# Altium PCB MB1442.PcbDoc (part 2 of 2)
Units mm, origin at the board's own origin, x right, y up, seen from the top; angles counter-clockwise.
Board outline 18.54 x 50.29 mm, 4 copper layers (Top Layer, Signal Layer 1, Signal Layer 2, Bottom Layer); 93 components, 78 nets, 322 pads, 169 vias.
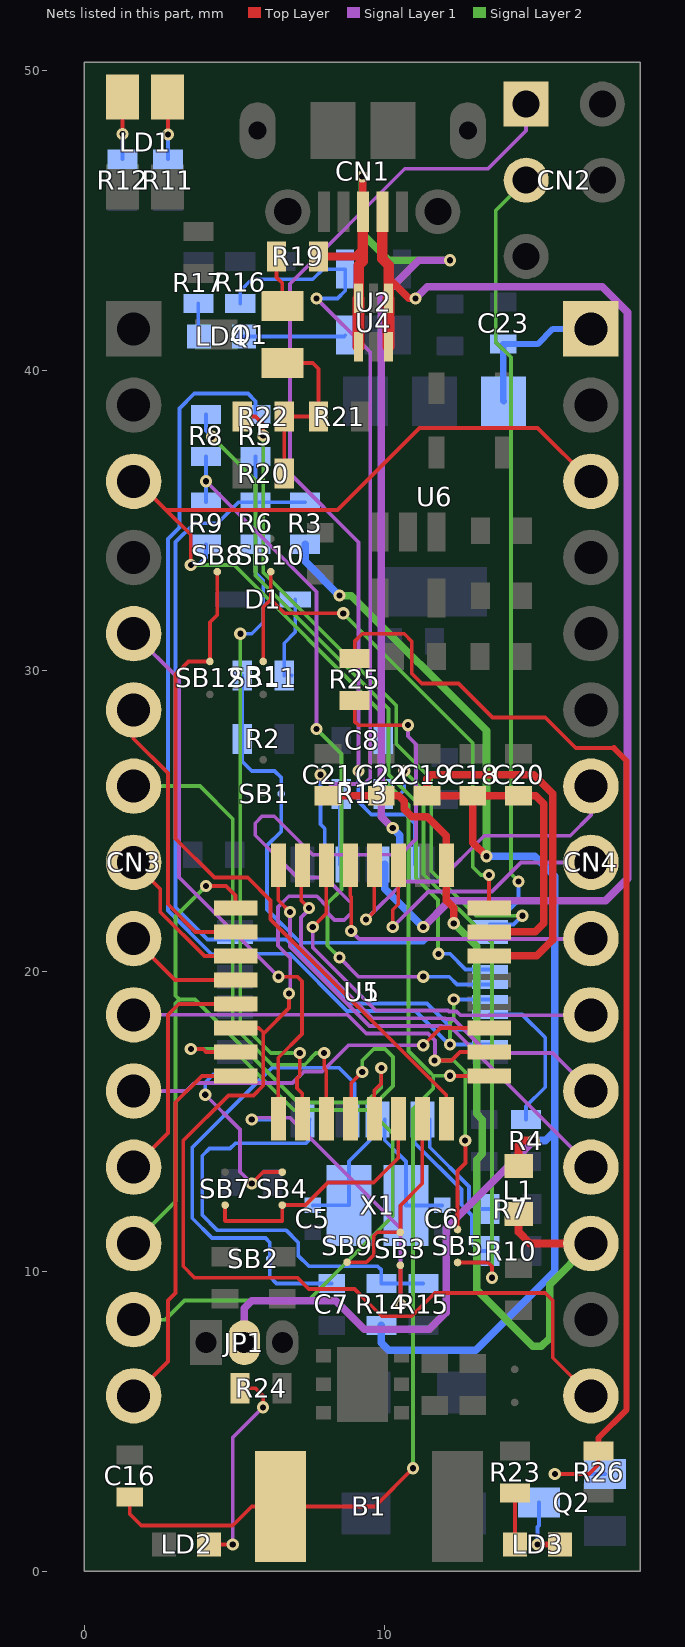
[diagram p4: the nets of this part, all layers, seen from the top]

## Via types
v1: diameter 0.406, hole 0.203, Top Layer to Bottom Layer, tented both sides, 169 vias

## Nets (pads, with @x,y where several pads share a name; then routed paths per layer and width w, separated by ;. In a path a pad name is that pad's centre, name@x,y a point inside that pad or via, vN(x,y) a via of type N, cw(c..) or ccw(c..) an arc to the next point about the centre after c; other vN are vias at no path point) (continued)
NetD1_2: D1.2 R1.1 | length 2.7
  Bottom Layer w0.127: R1.1@6.669,29.845 6.669,30.926 7.039,31.296 D1.2@7.039,32.385 ; R1.1@6.912,29.856 R1.1@6.923,29.845
NetLD1_2: LD1.2 R12.2 | length 2.1
  Top Layer w0.127: v1(1.282,47.891) LD1.2@1.282,49.125
  Bottom Layer w0.127: R12.2@1.282,47.055 v1(1.282,47.891)
NetLD1_3: LD1.3 R11.2 | length 2.1
  Top Layer w0.127: v1(2.794,47.879) LD1.3@2.794,49.113
  Bottom Layer w0.127: R11.2@2.794,47.055 v1(2.794,47.879)
NetLD2_1: LD2.1 R24.1 | length 7
  Top Layer w0.127: LD2.1@4.167,0.889 v1(4.953,0.889) ; R24.1@5.2,6.096 5.715,6.096 5.969,5.842 5.969,5.468 v1(5.962,5.461)
  Signal Layer 1 w0.127: v1(4.953,0.889) 4.953,4.452 v1(5.962,5.461)
NetLD3_1: LD3.1 R23.1 | length 1.7
  Top Layer w0.127: LD3.1@14.363,0.889 R23.1@14.363,2.602
NetLD3_2: LD3.2 Q2.3 | length 2.2
  Top Layer w0.203: v1(15.113,0.889) LD3.2@15.863,0.889
  Bottom Layer w0.127: v1(15.113,0.889) 15.113,1.481 15.156,1.524 Q2.3@15.156,2.286
NetLD4_1: LD4.1 R17.1 | length 1.1
  Bottom Layer w0.127: R17.1@3.807,42.245 3.807,41.163 LD4.1@3.822,41.148
NetLD4_2: LD4.2 U2.3 | length 3.4
  Bottom Layer w0.127: LD4.2@5.322,41.148 8.659,41.148 U2.3@8.702,41.191
NetQ1_1: Q1.1 R20.1 R21.2 R22.1 | length 6
  Top Layer w0.127: Q1.1@6.604,40.259 7.62,40.259 7.809,40.07 R21.2@7.809,38.481 R22.1@6.669,38.481 R20.1@6.669,36.576 ; Q1.1@6.604,40.518 Q1.1@6.669,40.453
NetQ1_2: Q1.2 R19.2 | length 1.7
  Top Layer w0.127: R19.2@6.412,43.815 6.412,43.118 6.604,42.926 Q1.2@6.604,42.159
NetQ2_1: Q2.1 R25.2 R26.1 | length 39.2
  Top Layer w0.127: R25.2@9.017,30.418 9.017,30.988 9.271,31.242 10.668,31.242 10.922,30.988 10.922,29.913 11.252,29.583 12.476,29.583 13.611,28.448 15.367,28.448 16.383,27.432 17.653,27.432 ; v1(15.687,3.236) 16.825,3.236 17.145,3.556 R26.1@17.145,4.002
  Top Layer w0.2: R26.1@17.145,4.002 17.145,4.445 18.083,5.383 18.083,27.002 17.653,27.432
  Bottom Layer w0.127: v1(15.687,3.236) Q2.1@17.356,3.236
NetR1_2: R1.2 R2.1 SB1.2 U1.39 | length 16.9
  Bottom Layer w0.127: R1.2@5.269,29.845 R2.1@5.269,27.734 5.269,26.989 5.588,26.67 6.35,26.67 6.569,26.451 SB1.2@6.569,25.908 6.569,24.652 6.096,24.179 6.096,22.054 7.208,20.942 11.318,20.942 11.455,21.079 13.496,21.079 U1.39@13.521,21.054
NetR4_2: R4.2 U1.44 | length 5.2
  Bottom Layer w0.127: U1.44@13.521,18.554 14.593,18.554 15.367,17.78 15.367,16.129 14.732,15.494 R4.2@14.732,15.051
NetR7_2: R7.2 U1.2 | length 4.1
  Bottom Layer w0.127: U1.2@11.521,15.054 11.521,14.129 12.827,12.823 12.827,12.319 13.081,12.065 R7.2@13.524,12.065
NetR10_2: R10.2 U1.3 | length 5.6
  Bottom Layer w0.127: U1.3@11.021,15.054 11.021,14.269 12.573,12.717 12.573,12.214 12.929,11.857 12.929,10.922 13.183,10.668 R10.2@13.524,10.668
NetR13_1: R13.1 U1.29 | length 2.4
  Bottom Layer w0.127: U1.29@8.521,23.554 8.521,25.858 R13.1@8.571,25.908
NetR14_2: R14.2 R15.2 U1.10 | length 15.3
  Bottom Layer w0.127: U1.10@7.521,15.054 7.493,15.026 7.493,14.364 7.393,14.263 5.041,14.263 4.862,14.084 4.178,14.084 3.937,13.843 3.937,11.866 4.445,11.358 6.74,11.358 7.134,10.964 7.134,10.519 7.493,10.16 9.779,10.16 9.906,10.033 R14.2@9.906,9.59 R15.2@11.303,9.59
NetSB3_2: SB3.2 U1.12 | length 11.3
  Top Layer w0.127: v1(10.541,8.89) SB3.2@10.541,10.195
  Signal Layer 1 w0.127: v1@5.588,15.113 6.858,15.113 10.541,11.43 v1(10.541,8.89)
  Bottom Layer w0.127: v1(5.588,15.054) U1.12@6.521,15.054
NetSB4_2: SB4.2 U1.13 | length 6.4
  Top Layer w0.127: v1(5.588,12.919) 5.969,13.3 SB4.2@6.604,13.3
  Signal Layer 1 w0.127: v1(4.038,15.877) 5.194,14.721 5.194,13.313 v1(5.588,12.919)
  Bottom Layer w0.127: v1@4.063,15.852 4.085,15.875 4.084,15.877 v1(4.038,15.877) 4.038,16.29 4.302,16.554 U1.13@5.021,16.554
PA1: CN3.10 SB5.2 U5.2 | length 20.5
  Top Layer w0.127: v1(11.684,17.018) 12.241,17.018 12.527,17.304 U5.2@13.496,17.304 ; SB5.2@12.446,11.387 12.446,13.335 12.713,13.602 12.713,14.465 12.7,14.453 v1(12.7,14.351)
  Signal Layer 1 w0.127: CN3.10@2.159,18.034 CN3.10@1.651,18.542 8.78,18.542 9.402,17.92 11.466,17.92 11.697,17.689 11.697,17.031 v1(11.684,17.018)
  Signal Layer 2 w0.127: v1(11.684,17.018) 12.319,17.018 12.7,16.637 v1(12.7,14.351)
PA2: CN3.11 U5.3 | length 12.7
  Top Layer w0.127: v1(11.303,17.526) 11.881,18.104 U5.3@13.496,18.104
  Signal Layer 1 w0.127: CN3.11@1.651,16.002 3.416,16.002 3.685,16.271 6.951,16.271 7.33,16.65 7.935,16.65 8.812,17.526 v1(11.303,17.526)
PB0: CN4.12 U5.16 | length 15.9
  Top Layer w0.127: U5.16@6.471,23.529 6.471,22.358 v1(6.858,21.971)
  Signal Layer 1 w0.127: v1(6.858,21.971) 6.858,20.823 9.507,18.174 11.92,18.174 11.946,18.148 12.205,18.148 CN4.12@16.891,13.462
PB1: CN4.11 U5.15 | length 14.6
  Top Layer w0.127: U5.15@7.271,23.529 7.239,23.497 7.239,22.352 v1(7.493,22.098)
  Signal Layer 1 w0.127: v1@7.514,22.098 v1(7.493,22.098) 7.493,22.049 7.226,21.783 7.226,20.814 9.612,18.428 12.025,18.428 12.051,18.402 12.31,18.402 13.44,17.272 15.621,17.272 CN4.11@16.891,16.002
PB2: CN4.10 U5.14 | length 13.2
  Top Layer w0.127: v1(7.62,21.463) 8.071,21.914 U5.14@8.071,23.529
  Signal Layer 1 w0.127: v1(7.62,21.463) 7.62,20.779 9.718,18.682 12.131,18.682 12.156,18.656 12.415,18.656 12.542,18.529 16.891,18.529 CN4.10@16.891,18.542
PB3: CN4.9 U5.13 | length 10.3
  Top Layer w0.127: U5.13@8.871,23.529 8.871,22.498 8.903,22.466 8.903,21.339 v1(8.9,21.336)
  Signal Layer 1 w0.127: v1@8.89,21.336 v1(8.9,21.336) 9.167,21.069 16.878,21.069 CN4.9@16.891,21.082
PB4: CN4.7 U5.12 | length 11.8
  Top Layer w0.127: v1(9.398,21.717) 9.671,21.99 U5.12@9.671,23.529
  Signal Layer 1 w0.127: v1(9.398,21.717) 10.668,22.987 11.811,22.987 13.335,24.511 16.202,24.511 16.891,25.2 CN4.7@16.891,26.162
PB5: CN4.8 U5.11 | length 9.6
  Top Layer w0.127: v1(10.287,21.463) 10.287,22.041 10.471,22.225 U5.11@10.471,23.529
  Signal Layer 1 w0.127: v1(10.287,21.463) 11.479,22.655 13.589,22.655 14.556,23.622 CN4.8@16.891,23.622
PC1: CN3.6 U5.18 | length 9.6
  Top Layer w0.127: CN3.6@1.651,28.702 1.651,27.74 2.794,26.597 2.794,22.225 3.715,21.304 U5.18@5.046,21.304
PC2: CN3.8 U5.19 | length 5.1
  Top Layer w0.127: CN3.8@1.651,23.622 2.54,22.733 2.54,21.971 4.007,20.504 U5.19@5.046,20.504
PC3: CN3.9 U5.20 | length 4
  Top Layer w0.127: CN3.9@1.651,21.082 3.029,19.704 U5.20@5.046,19.704
PC4: CN3.12 U5.21 | length 8
  Top Layer w0.127: CN3.12@1.651,13.462 2.794,14.605 2.794,18.542 3.156,18.904 U5.21@5.046,18.904
PC5: CN4.15 R25.1 U5.22 | length 52.9
  Top Layer w0.127: U5.22@5.046,18.104 5.823,18.104 5.969,17.958 5.969,17.907 ; v1(6.833,19.253) 6.833,18.771 5.969,17.907 ; R25.1@9.017,29.018 9.017,28.321 9.144,28.194 v1(10.795,28.194) ; CN4.15@16.891,5.842 15.621,7.112 15.621,9.017 15.367,9.271 11.685,9.271 10.91,8.496 9.919,8.496 9.011,9.404 7.487,9.404 7.112,9.779 3.683,9.779 3.302,10.16 3.302,14.351 4.808,15.857 5.644,15.857 5.969,16.183 5.969,17.907
  Signal Layer 1 w0.127: v1(6.833,19.253) 6.871,19.291 6.871,20.434 6.464,20.841 6.464,22.134 6.822,22.492 7.756,22.492 8.115,22.132 8.115,21.935 8.346,21.704 8.672,21.704 8.903,21.935 8.903,22.261 8.05,23.114 7.112,23.114 5.702,24.524 5.702,24.928 5.933,25.159 6.337,25.159 7.62,23.876 10.541,23.876 11.062,24.397 11.062,27.559 10.795,27.826 v1(10.795,28.194)
PC6: CN3.14 U5.23 U5.28 | length 27.7
  Top Layer w0.127: v1(3.556,17.399) 3.969,17.399 4.064,17.304 U5.23@5.046,17.304 ; U5.28@8.871,15.079 8.903,15.111 8.903,16.269 v1(9.271,16.637)
  Signal Layer 2 w0.127: CN3.14@1.651,8.382 2.712,8.382 3.347,9.017 7.472,9.017 10.287,11.832 10.287,14.583 9.503,15.367 ; v1(3.556,17.399) 4.953,17.399 6.985,15.367 9.503,15.367 ; v1(9.271,16.637) 9.271,17.018 9.652,17.399 10.033,17.399 10.3,17.132 10.3,16.163 9.503,15.367
PC7: CN3.15 U5.24 | length 12.7
  Top Layer w0.127: CN3.15@1.651,5.842 2.794,6.985 2.794,9.017 3.048,9.271 3.048,15.625 3.927,16.504 U5.24@5.046,16.504
PD0: CN3.5 U5.25 | length 19.2
  Top Layer w0.127: U5.25@6.471,15.079 6.471,17.112 7.264,17.905 7.264,19.66 7.112,19.812 v1(6.477,19.812)
  Signal Layer 1 w0.127: CN3.5@1.651,31.242 3.162,29.731 3.162,23.127 v1(6.477,19.812)
PD2: CN3.7 U5.27 | length 16.6
  Top Layer w0.127: v1(8.001,17.272) 8.001,16.764 8.071,16.694 U5.27@8.071,15.079
  Signal Layer 2 w0.127: CN3.7@1.651,26.162 3.859,26.162 4.953,25.068 4.953,18.182 6.256,16.878 7.351,16.878 7.582,17.109 7.582,17.129 7.725,17.272 v1(8.001,17.272)
PD4: CN3.13 U5.17 U5.29 | length 25.3
  Top Layer w0.127: v1(4.064,22.834) 4.725,22.834 5.046,22.513 U5.17@5.046,22.104 ; U5.29@9.671,15.079 9.671,16.021 9.906,16.256 v1(9.906,16.764)
  Signal Layer 2 w0.127: CN3.13@1.651,10.922 3.048,12.319 3.048,18.923 3.175,19.05 ; v1(4.064,22.834) 3.048,21.818 3.048,19.177 3.175,19.05 ; v1(9.906,16.764) 9.906,16.129 9.398,15.621 7.125,15.621 3.696,19.05 3.175,19.05
PD7: SB8.2 SB12.2 U5.32 | length 23.6
  Top Layer w0.127: SB8.2@4.445,33.302 SB8.2@4.438,33.309 4.438,31.87 4.191,31.623 SB12.2@4.191,30.318 3.483,30.318 3.048,29.883 3.048,24.407 4.341,23.114 5.453,23.114 6.217,22.35 6.217,21.723 12.071,15.869 U5.32@12.071,15.079
PF4: SB10.2 SB11.2 U5.8 | length 17.7
  Top Layer w0.127: SB11.2@5.969,30.318 5.969,32.131 6.223,32.385 ; SB10.2@6.223,33.309 6.223,32.385 ; v1(8.636,31.921) 6.687,31.921 6.223,32.385 ; U5.8@13.496,22.104 v1(13.496,23.2)
  Signal Layer 2 w0.127: v1(8.636,31.921) 12.954,27.603 12.954,23.467 13.221,23.2 v1(13.496,23.2)
PWR_ENn: R16.1 U1.28 U2.4 | length 27.7
  Signal Layer 1 w0.127: v1(7.747,42.418) 9.538,40.627 9.538,26.429 9.338,26.229 8.188,26.229 v1(7.874,26.543)
  Bottom Layer w0.127: R16.1@5.204,42.248 5.204,42.669 5.588,43.053 7.62,43.053 7.958,43.391 U2.4@8.702,43.391 8.702,42.672 8.448,42.418 v1(7.747,42.418) ; v1(7.874,26.543) 7.874,24.892 8.021,24.745 U1.28@8.021,23.554
ST_LINK_SWCLK: CN2.3 U1.37 | length 25.8
  Signal Layer 2 w0.127: v1(14.478,22.987) 14.224,23.241 14.224,40.454 13.716,40.962 13.716,45.339 CN2.3@14.732,46.355
  Bottom Layer w0.127: U1.37@13.521,22.054 14.18,22.054 14.478,22.352 v1(14.478,22.987)
ST_LINK_SWDIO: CN2.1 U1.34 | length 32.6
  Signal Layer 1 w0.127: v1(9.144,26.67) 9.144,34.29 6.858,36.576 6.858,42.905 10.689,46.736 13.462,46.736 14.732,48.006 CN2.1@14.732,48.895
  Bottom Layer w0.127: v1(9.144,26.67) 9.144,25.646 9.572,25.217 10.724,25.217 11.021,24.92 U1.34@11.021,23.554
ST_LINK_USB_D_N: CN1.2 U1.32 U4.1 U4.6 | length 42.3
  Top Layer w0.254: 10.152,43.093 10.827,42.418 v1(11.049,42.418)
  Top Layer w0.35: CN1.2@9.937,45.306 9.937,43.736 10.157,43.516 10.157,43.098 10.152,43.093 U4.1@10.152,42.418
  Top Layer w0.4: U4.6@10.152,40.808 U4.1@10.152,42.418
  Signal Layer 1 w0.254: v1(11.049,42.418) 11.43,42.799 17.272,42.799 18.11,41.961 18.11,23.071 17.377,22.337 12.177,22.337 v1(11.303,21.463)
  Bottom Layer w0.254: U1.32@10.021,23.554 10.021,22.745 v1(11.303,21.463)
ST_LINK_USB_D_P: CN1.3 R19.1 U1.33 U4.3 U4.4 | length 34.5
  Top Layer w0.254: R19.1@7.812,43.815 9.033,43.815 9.287,44.069 ; v1(9.271,46.482) 9.287,46.466 CN1.3@9.287,45.306 ; v1(12.192,43.688) v1@12.2,43.68
  Top Layer w0.35: U4.3@9.152,42.418 9.152,43.093 9.147,43.098 9.147,43.516 9.287,43.656 9.287,44.069 CN1.3@9.287,45.306
  Top Layer w0.4: U4.4@9.152,40.808 U4.3@9.152,42.418
  Signal Layer 1 w0.254: v1(10.287,24.765) 9.906,25.146 9.906,42.444 11.15,43.688 v1(12.192,43.688)
  Signal Layer 2 w0.254: v1(9.271,46.482) 9.271,44.577 10.16,43.688 v1(12.192,43.688)
  Bottom Layer w0.254: v1(10.287,24.765) 10.521,24.531 U1.33@10.521,23.554
STLK_OSC_IN: C6.1 U1.5 X1.1 | length 4.4
  Bottom Layer w0.127: U1.5@10.021,15.054 10.021,14.363 10.729,13.655 X1.1@10.729,12.192 10.731,12.19 C6.1@11.938,12.19
STLK_OSC_OUT: C5.1 U1.6 X1.2 | length 4.4
  Bottom Layer w0.127: C5.1@7.62,12.19 7.622,12.192 X1.2@8.829,12.192 8.829,13.659 9.521,14.351 U1.6@9.521,15.054
STLK_RST: C7.2 SB2.2 U1.7 | length 16.5
  Bottom Layer w0.127: C7.2@8.255,9.59 6.412,9.59 6.188,9.814 SB2.2@6.188,10.414 6.188,10.957 6.041,11.104 4.263,11.104 3.604,11.763 3.604,14.124 5.694,16.214 5.7,16.214 5.812,16.325 5.812,16.331 6.257,16.777 8.496,16.777 9.021,16.252 U1.7@9.021,15.054
SWIM: R3.1 R5.2 R6.1 U1.22 U1.45 | length 30.7
  Bottom Layer w0.127: R5.2@5.715,37.146 R6.1@5.715,35.625 ; R3.1@7.366,35.625 R6.1@5.715,35.625 ; U1.45@13.521,18.054 12.299,18.054 11.43,18.923 8.868,18.923 6.737,21.054 U1.22@5.021,21.054 4.113,21.054 3.048,22.119 3.048,34.298 3.675,34.925 4.453,34.925 4.755,35.226 4.755,35.235 5.145,35.625 R6.1@5.715,35.625
SWIM_IN: R5.1 U1.21 U1.43 U1.46 | length 35.5
  Signal Layer 2 w0.127: v1(12.192,17.554) 12.192,18.288 12.319,18.415 v1(12.319,19.05)
  Bottom Layer w0.127: R5.1@5.715,38.546 5.715,38.989 5.461,39.243 3.672,39.243 3.175,38.746 3.175,34.785 2.794,34.404 2.794,22.013 4.253,20.554 U1.21@5.021,20.554 5.041,20.574 6.858,20.574 8.763,18.669 11.049,18.669 12.164,17.554 v1(12.192,17.554) U1.46@13.521,17.554 ; v1(12.319,19.05) 12.323,19.054 U1.43@13.521,19.054
SWIM_RST: R8.2 R9.1 U1.42 | length 25
  Signal Layer 1 w0.127: v1(4.064,36.322) 7.747,32.639 v1(7.747,28.067) ; v1(8.509,20.447) 9.144,19.812 v1(11.303,19.812)
  Signal Layer 2 w0.127: v1(7.747,28.067) 8.576,27.238 8.576,22.722 8.115,22.261 8.115,20.841 v1(8.509,20.447)
  Bottom Layer w0.127: R9.1@4.064,35.625 v1(4.064,36.322) R8.2@4.064,37.146 ; v1(11.303,19.812) 12.17,19.812 12.428,19.554 U1.42@13.521,19.554
SWIM_RST_IN: R8.1 U1.41 | length 23.1
  Signal Layer 2 w0.127: v1(4.265,37.803) 5.715,36.353 5.715,33.174 10.147,28.742 10.147,26.556 11.062,25.641 11.062,23.101 11.798,22.365 11.798,20.587 v1(11.811,20.574)
  Bottom Layer w0.127: R8.1@4.064,38.546 4.064,38.004 v1(4.265,37.803) ; v1(11.811,20.574) 12.192,20.574 12.712,20.054 U1.41@13.521,20.054
T_MCO: C8.2 R13.2 SB5.1 | length 22.8
  Top Layer w0.127: SB5.1@12.446,10.287 13.462,10.287 13.589,10.16 v1(13.589,9.779)
  Signal Layer 2 w0.127: v1(10.668,26.67) 11.316,26.022 11.316,23.228 13.589,20.955 v1(13.589,9.779)
  Bottom Layer w0.127: C8.2@9.971,27.686 R13.2@9.971,25.908 10.541,25.908 10.668,26.035 v1(10.668,26.67)
T_NRST: B1.1 C16.2 CN3.3 CN4.3 R9.2 U5.1 | length 68.1
  Top Layer w0.127: C16.2@1.524,2.475 1.524,1.905 1.905,1.524 4.953,1.524 5.588,2.159 B1.1@6.546,2.159 6.548,2.157 9.691,2.157 v1(10.963,3.429) ; CN3.3@1.651,36.322 1.778,36.322 2.73,35.369 ; v1(3.556,33.528) 3.556,34.544 2.73,35.369 ; v1(12.192,16.51) 12.198,16.504 U5.1@13.496,16.504 ; CN4.3@16.891,36.322 15.113,38.1 11.176,38.1 8.445,35.369 2.73,35.369
  Signal Layer 2 w0.127: v1(3.556,33.528) 5.002,33.528 9.893,28.636 9.893,26.45 10.808,25.536 10.808,17.338 11.51,16.635 11.635,16.51 ; v1(10.963,3.429) 10.963,15.408 11.635,16.08 11.635,16.51 ; v1(12.192,16.51) 11.635,16.51
  Bottom Layer w0.127: v1(3.556,33.528) 3.81,33.528 4.064,33.782 R9.2@4.064,34.225
T_SWIM: R6.2 U5.26 | length 21.3
  Top Layer w0.127: v1(7.188,17.272) 7.188,16.51 7.099,16.421 7.099,16.093 7.271,15.921 U5.26@7.271,15.079
  Signal Layer 2 w0.127: v1(5.207,31.242) 5.207,18.287 6.222,17.272 v1(7.188,17.272)
  Bottom Layer w0.127: v1(5.207,31.242) 5.588,31.242 5.969,31.623 5.969,33.02 5.715,33.274 R6.2@5.715,34.225
T_VCP_RX: SB3.1 SB9.1 U5.31 | length 6.7
  Top Layer w0.127: SB9.1@8.763,10.295 9.406,10.295 9.652,10.541 9.652,11.176 9.771,11.295 SB3.1@10.541,11.295 10.541,12.192 11.271,12.922 U5.31@11.271,15.079
T_VCP_TX: SB4.1 SB7.1 U5.30 | length 8.8
  Top Layer w0.127: SB7.1@4.699,12.2 4.699,11.684 4.712,11.671 6.591,11.671 6.604,11.684 SB4.1@6.604,12.2 7.374,12.2 8.128,12.954 9.652,12.954 10.471,13.773 U5.30@10.471,15.079
USB_RENUMn: R22.2 U1.38 | length 22.9
  Top Layer w0.127: R22.2@5.269,38.481 5.715,38.481 5.969,38.227 v1(5.969,37.846)
  Signal Layer 2 w0.127: v1(5.969,37.846) 5.969,33.279 10.401,28.847 10.401,27.572 11.57,26.403 11.57,23.334 13.059,21.844 v1(14.605,21.844)
  Bottom Layer w0.127: U1.38@13.521,21.554 14.315,21.554 v1(14.605,21.844)
VDD: C18.2 C19.1 C20.1 JP1.2 L1.2 R3.2 R14.1 U5.6 U5.7 | length 78.4
  Top Layer w0.254: v1(13.411,23.825) 12.954,24.282 C18.2@12.954,25.843 ; U5.6@13.496,20.504 15.089,20.504 15.621,21.036 15.621,25.908 14.986,26.543 11.557,26.543 11.427,26.413 C19.1@11.427,25.843 C18.2@12.954,25.843 ; U5.7@13.496,21.304 15.029,21.304 15.316,21.591 15.316,25.578 15.051,25.843 C20.1@14.478,25.843 C18.2@12.954,25.843 ; L1.2@14.478,13.5 14.478,14.209 14.62,14.351 v1(14.986,14.351)
  Signal Layer 1 w0.254: JP1.2@5.334,7.616 5.334,8.763 5.588,9.017 8.382,9.017 9.335,8.064 11.508,8.064 12.065,8.621 12.065,11.43 v1(14.986,14.351)
  Signal Layer 2 w0.254: v1(8.509,32.512) 8.902,32.512 13.411,28.002 v1(13.411,23.825)
  Bottom Layer w0.254: R3.2@7.366,34.225 7.366,33.655 v1(8.509,32.512) ; R14.1@9.906,8.19 9.906,7.62 10.16,7.366 13.05,7.366 15.684,10 15.684,23.157 15.017,23.825 v1(13.411,23.825) ; v1(14.986,14.351) 15.371,14.351 15.655,14.635
VDDA: C21.2 C22.1 CN4.13 L1.1 U5.9 | length 30.6
  Top Layer w0.254: C21.2@8.125,25.843 C22.1@9.903,25.843 10.479,25.843 10.668,25.654 10.668,25.4 10.922,25.146 11.43,25.146 12.071,24.505 U5.9@12.071,23.529 12.071,22.352 12.319,22.104 v1(12.319,21.59) ; L1.1@14.478,11.9 14.478,11.303 14.859,10.922 CN4.13@16.891,10.922
  Signal Layer 2 w0.254: v1(12.319,21.59) 13.081,20.828 13.081,15.24 13.271,15.05 13.271,13.906 13.081,13.716 13.081,9.371 14.959,7.493 15.24,7.493 15.517,7.77 15.517,9.548 CN4.13@16.891,10.922
VIN: C23.2 CN4.1 U6.3 | length 5
  Bottom Layer w0.203: U6.3@13.984,38.989 13.97,39.003 C23.2@13.97,40.894 15.113,40.894 15.621,41.402 CN4.1@16.891,41.402
pads on no net: CN2.5 U1.4 U1.11 U1.14 U1.15 U1.16 U1.17 U1.18 U1.19 U1.25 U1.26 U1.27 U1.31 U1.40 U7.3 U7.5
copper on no net:
  other v1: 2.159,7.112

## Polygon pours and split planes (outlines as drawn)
GND on Signal Layer 2 "GND_L03_P004" (solid, remove dead copper, pour order 4): 0.254,50.038 18.288,50.038 18.288,0.254 0.254,0.254
GND on Signal Layer 1 "GND_L02_P008" (solid, remove dead copper, pour order 8): 0.254,50.038 18.288,50.038 18.288,0.254 0.254,0.254
GND on Top Layer "GND_L01_P000" (solid, remove dead copper, pour order 0): 0.254,50.038 0.381,50.038 18.288,50.038 18.288,0.254 18.415,0.127 0.127,0.127 0.127,50.038
GND on Bottom Layer "GND_L04_P002" (solid, remove dead copper, pour order 2): 18.288,50.038 18.288,0.254 18.415,0.127 0.127,0.127 0.127,50.038

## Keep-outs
Keep-Out Layer:
  the board outline again, w0.127

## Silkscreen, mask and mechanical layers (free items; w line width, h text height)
Top Overlay:
  text "CN3" at 0.508,43.053 h1.02
  text "CN4" at 16.002,43.053 h1.02
  text "D1/TX" at 2.667,42.672 h1.02 r270
  text "VIN" at 15.24,42.164 h1.02 r270
  text "D0/RX" at 2.667,39.878 h1.02 r270
  text "GND" at 15.24,39.878 h1.02 r270
  text "J" at 10.541,39.751 h8
  text "RST" at 15.24,37.211 h1.02 r270
  text "RST" at 2.667,37.084 h1.02 r270
  text "GND" at 2.667,34.671 h1.02 r270
  text "5V" at 15.24,34.29 h1.02 r270
  text "A7" at 15.24,31.877 h1.02 r270
  text "D2" at 2.667,31.75 h1.02 r270
  text "D3" at 2.667,29.337 h1.02 r270
  text "A6" at 15.24,29.337 h1.02 r270
  text "D4" at 2.667,26.797 h1.02 r270
  text "A5" at 15.24,26.67 h1.02 r270
  text "D5" at 2.667,24.13 h1.02 r270
  text "A4" at 15.24,24.13 h1.02 r270
  text "A3" at 15.24,21.717 h1.02 r270
  text "D6" at 2.667,21.463 h1.02 r270
  text "D7" at 2.667,19.05 h1.02 r270
  text "A2" at 15.24,19.05 h1.02 r270
  text "A1" at 15.24,16.764 h1.02 r270
  text "D8" at 2.667,16.51 h1.02 r270
  text "A0" at 15.24,14.478 h1.02 r270
  text "D9" at 2.667,13.97 h1.02 r270
  text "MB1442B" at 8.509,13.335 h1.02
  text "REF" at 15.24,12.192 h1.02 r270
  text "D10" at 2.667,11.684 h1.02 r270
  text "D11" at 2.667,9.271 h1.02 r270
  text "3V3" at 15.24,9.271 h1.02 r270
  text "D12" at 2.667,6.731 h1.02 r270
  text "D13" at 15.24,6.731 h1.02 r270
  text "RST" at 3.861,2.286 h1.02
Bottom Overlay:
  drawing of 800 lines, arcs and shapes, not listed
  text "E" at 10.795,27.559 h8
  text "www.st.com/stm8nucleo" at 14.732,17.018 h1.02 r270
  text "3V3" at 0.889,1.905 h0.76 r90
  text "VDD" at 2.032,1.905 h0.76 r90
  text "5V" at 3.175,1.905 h0.76 r90
M1-Board Shape:
  the board outline again, w0.127
M2-Board Dimensions:
  the board outline again, w0.127
Drill Drawing:
  drawing of 385 lines, arcs and shapes, not listed
  text "PCB SPECIFICATIONS :" at -45.678,103.608 h3
  text "PCB : TYPE 3" at 102.733,103.376 h3
  text "A.   MATERIAL :" at -45.678,99.608 h3
  text "FR-4" at -7.178,99.608 h3
  text "TG-170" at 9.322,99.608 h3
  text "X  TG-150" at 27.571,99.608 h3
  text "TG-140" at 43.572,99.608 h3
  text "ASPECT-RATIO, AXE Z :" at 102.733,97.876 h3
  text "B.   MATERIAL FAMILY :" at -45.678,96.608 h3
  text "N/A" at -7.178,96.608 h3
  text "C.   SOLDERMASK COLOR :" at -45.678,93.608 h3
  text "GREEN" at -7.178,93.608 h3
  text "X  WHITE" at 9.322,93.608 h3
  text "RED" at 27.571,93.608 h3
  text "BLACK" at 43.572,93.608 h3
  text "6:1 to 8:1 / LEVEL \"B\"" at 102.752,91.129 h3
  text "D.   SILKSCREEN COLOR :" at -45.678,90.608 h3
  text "WHITE" at -7.178,90.608 h3
  text "YELLOW" at 9.322,90.608 h3
  text "BLACK" at 27.571,90.608 h3
  text "X  Blue ink PANTONE 2955" at 43.571,90.608 h3
  text "E.   SURFACE FINISH :" at -45.678,87.608 h3
  text "X  ENIG" at -7.178,87.608 h3
  text "IMMERSION SILVER" at 9.322,87.608 h3
  text "IMMERSION TIN" at 43.572,87.608 h3
  text "MINIMUM PARAMETERS" at 102.779,85.528 h3
  text "HASL" at -7.178,84.608 h3
  text "HASL (PB-FREE)" at 9.322,84.608 h3
  text "GOLDEN FINGER" at 43.572,84.608 h3
  text "F.   IMPEDANCE CONTROL :" at -45.678,81.608 h3
  text "NO" at -7.178,81.608 h3
  text "X  YES  (SEE IMPEDANCE TABLE FOR DETAIL INFORMATION)" at 9.322,81.608 h3
  text "DEFAULT" at 102.779,80.028 h3
  text "G.   THROUGH VIA :" at -45.678,78.608 h3
  text "PLUG THE VIAS WHICH ARE COVERED WITH SOLDERMASK ONE OR TWO SIDE." at -7.178,78.608 h3
  text "PLUG MATERIAL :" at -7.178,75.608 h3
  text "X  SOLDERMASK" at 18.322,75.608 h3
  text "NON-CONDUCTIVE EPOXY." at 43.572,75.608 h3
  text "TRACKS : 0.127mm           / GAPS : 0.127mm" at 102.779,74.278 h3
  text "H.   STACK-UP :" at -45.678,72.608 h3
  text "SEE LAYER STACK-UP SEQUENCE FOR OVERALL THICKNESS." at -7.178,72.608 h3
  text "IMPEDANCE TABLE   USB HS STLINK" at 115.39,62.034 h3
  text "Layer" at 33.85,62.026 h2
  text "Name" at 42.219,62.026 h2
  text "Material" at 58.402,62.026 h2
  text "Thickness" at 72.945,62.026 h2
  text "Constant" at 84.891,62.026 h2
  text "Board Layer Stack" at 95.946,62.026 h2
  text "Top Overlay" at 42.219,58.026 h2
  text "LAYER" at 119.64,57.034 h3
  text "TRACE" at 135.89,57.034 h3
  text "SPACING" at 146.39,57.034 h3
  text "IMPEDANCE" at 159.89,57.034 h3
  text "IMPEDANCE" at 176.89,57.034 h3
  text "TOL." at 195.64,57.034 h3
  text "(mm)" at 149.715,54.559 h2.5
  text "(mm)" at 137.89,54.509 h2.5
  text "(Single ended)" at 160.39,54.284 h2.5
  text "(Differential)" at 178.14,54.284 h2.5
  text "Top Solder" at 42.219,54.026 h2
  text "Solder Resist" at 58.402,54.026 h2
  text "0,010mm" at 72.945,54.026 h2
  text "3,5" at 84.891,54.026 h2
  text "+/- 15%" at 194.695,50.644 h3
  text "0.155" at 136.865,50.559 h3
  text "0.226" at 148.89,50.534 h3
  text "TOP" at 115.87,50.519 h3
  text "n/a" at 163.245,50.469 h3
  text "90 ohm" at 179.331,50.293 h3
  text "1" at 33.85,50.026 h2
  text "Top Layer" at 42.219,50.026 h2
  text "Copper" at 58.402,50.026 h2
  text "0,036mm" at 72.945,50.026 h2
  text "+/- 15%" at 194.7,47.129 h3
  text "0.130" at 136.87,47.044 h3
  text "0.251" at 148.895,47.019 h3
  text "LAYER 1" at 117.815,46.984 h3
  text "90 ohm" at 179.331,46.991 h3
  text "n/a" at 163.25,46.954 h3
  text "Dielectric 1" at 42.219,46.026 h2
  text "FR-4" at 58.402,46.026 h2
  text "0,320mm" at 72.945,46.026 h2
  text "4,8" at 84.891,46.026 h2
  text "2" at 33.848,42.026 h2
  text "Signal Layer 1" at 42.219,42.026 h2
  text "Copper" at 58.402,42.026 h2
  text "0,036mm" at 72.945,42.026 h2
  text "Dielectric 3" at 42.219,38.026 h2
  text "FR-4" at 58.402,38.026 h2
  text "0,320mm" at 72.945,38.026 h2
  text "4,8" at 84.891,38.026 h2
  text "3" at 33.85,34.026 h2
  text "Signal Layer 2" at 42.219,34.026 h2
  text "Copper" at 58.402,34.026 h2
  text "0,036mm" at 72.945,34.026 h2
  text "Dielectric 2" at 42.219,30.026 h2
  text "FR-4" at 58.402,30.026 h2
  text "0,320mm" at 72.945,30.026 h2
  text "4,8" at 84.891,30.026 h2
  text "4" at 33.85,26.026 h2
  text "Bottom Layer" at 42.219,26.026 h2
  text "Copper" at 58.402,26.026 h2
  text "0,036mm" at 72.945,26.026 h2
  text "Bottom Solder" at 42.219,22.026 h2
  text "Solder Resist" at 58.402,22.026 h2
  text "0,010mm" at 72.945,22.026 h2
  text "3,5" at 84.891,22.026 h2
  text "Bottom Overlay" at 42.219,18.026 h2
  text "Symbol" at 34.055,13.015 h2.16
  text "Count" at 42.521,13.015 h2.16
  text "Hole Size" at 51.324,13.015 h2.16
  text "Plated" at 66.925,13.015 h2.16
  text "Hole Type" at 74.358,13.015 h2.16
  text "Drill Layer Pair" at 85.175,13.015 h2.16
  text "Via/Pad" at 105.679,13.015 h2.16
  text "Pad Shape" at 114.546,13.015 h2.16
  text "Template" at 126.126,13.015 h2.16
  text "Description" at 152.126,13.015 h2.16
  text "Hole Tolerance (+)" at 163.757,13.015 h2.16
  text "Hole Tolerance (-)" at 181.837,13.015 h2.16
  text "Hole Length" at 199.43,13.015 h2.16
  text "Routed Path Length" at 214.983,13.015 h2.16
  text "2" at 42.521,9.28 h1.8
  text "23,62mil (0,60mm)" at 51.324,9.28 h1.8
  text "PTH" at 66.925,9.28 h1.8
  text "Slot" at 74.358,9.28 h1.8
  text "Top Layer - Bottom Layer" at 85.175,9.28 h1.8
  text "Pad" at 105.679,9.28 h1.8
  text "Rounded" at 114.546,9.28 h1.8
  text "r190_120h60_130r100m195_125" at 126.126,9.28 h1.8
  text "51,18mil (1,30mm)" at 199.43,9.28 h1.8
  text "27,56mil (0,70mm)" at 214.983,9.28 h1.8
  text "3" at 42.521,5.545 h1.8
  text "27,56mil (0,70mm)" at 51.324,5.545 h1.8
  text "PTH" at 66.925,5.545 h1.8
  text "Round" at 74.358,5.545 h1.8
  text "Top Layer - Bottom Layer" at 85.175,5.545 h1.8
  text "Pad" at 105.679,5.545 h1.8
  text "(Mixed)" at 114.546,5.545 h1.8
  text "(Mixed)" at 126.126,5.545 h1.8
  text "-" at 199.43,5.545 h1.8
  text "-" at 214.983,5.545 h1.8
  text "7" at 42.521,1.81 h1.8
  text "35,43mil (0,90mm)" at 51.324,1.81 h1.8
  text "PTH" at 66.925,1.81 h1.8
  text "Round" at 74.358,1.81 h1.8
  text "Top Layer - Bottom Layer" at 85.175,1.81 h1.8
  text "Pad" at 105.679,1.81 h1.8
  text "(Mixed)" at 114.546,1.81 h1.8
  text "(Mixed)" at 126.126,1.81 h1.8
  text "-" at 199.43,1.81 h1.8
  text "-" at 214.983,1.81 h1.8
  text "30" at 42.521,-1.925 h1.8
  text "43,31mil (1,10mm)" at 51.324,-1.925 h1.8
  text "PTH" at 66.925,-1.925 h1.8
  text "Round" at 74.358,-1.925 h1.8
  text "Top Layer - Bottom Layer" at 85.175,-1.925 h1.8
  text "Pad" at 105.679,-1.925 h1.8
  text "Rounded" at 114.546,-1.925 h1.8
  text "(Mixed)" at 126.126,-1.925 h1.8
  text "-" at 199.43,-1.925 h1.8
  text "-" at 214.983,-1.925 h1.8
  text "169" at 42.521,-5.66 h1.8
  text "8,00mil (0,20mm)" at 51.324,-5.66 h1.8
  text "PTH" at 66.925,-5.66 h1.8
  text "Round" at 74.358,-5.66 h1.8
  text "Top Layer - Bottom Layer" at 85.175,-5.66 h1.8
  text "Via" at 105.679,-5.66 h1.8
  text "Rounded" at 114.546,-5.66 h1.8
  text "v41h20m0mx0" at 126.126,-5.66 h1.8
  text "-" at 199.43,-5.66 h1.8
  text "-" at 214.983,-5.66 h1.8
  text "211 Total" at 42.521,-9.395 h1.8
  text "Slot definitions :" at 34.055,-12.01 h1.8
  text "Routed Path Length" at 46.345,-12.01 h1.8
  text "= Calculated from tool start centre position to tool end centre position." at 61.569,-12.01 h1.8
  text "Hole Length" at 46.345,-13.504 h1.8
  text "= Routed Path Length + Tool Size = Slot length as defined in the PCB layout" at 55.918,-13.504 h1.8

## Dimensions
0,50.292 to 0,0 on M2-Board Dimensions
0,50.292 to 18.542,50.292 on M2-Board Dimensions
1.651,5.842 to 16.891,5.842 on M2-Board Dimensions
1.651,5.842 to 0,0 on M2-Board Dimensions
0,0 to 1.651,5.842 on M2-Board Dimensions
18.542,0 to 16.891,5.842 on M2-Board Dimensions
